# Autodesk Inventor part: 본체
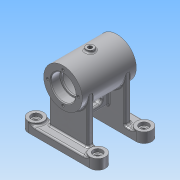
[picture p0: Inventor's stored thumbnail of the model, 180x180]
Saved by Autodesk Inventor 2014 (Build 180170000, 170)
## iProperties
Created: 2015-11
Part Number: 본체
Material: 알루미늄 6061
Document SubType Name: Modeling
Designer: 103-07
Density: 2.71 g/cm^3
Appearance: 알루미늄 - 평지
Mass: 359.155 g
Surface Area: 459.458 cm^2
Volume: 132.529 cm^3
Author: 103-07
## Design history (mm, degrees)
sketch "스케치1"
  geometry: L1 (-40, 40)-(40, 40); L2 (-40, 20)-(40, 20); L3 (-40, -20)-(40, -20); L4 (-40, -40)-(40, -40); A1 r 10 centre (-40, 30) between (-40, 40) and (-40, 20); A2 r 10 centre (40, 30) between (40, 40) and (40, 20); A3 r 10 centre (-40, -30) between (-40, -20) and (-40, -40); A4 r 10 centre (40, -30) between (40, -20) and (40, -40); 3 further points
  constraints: 8 end point, 8 point on circle, 7 tangent, 4 centre point, 3 equal radius, 2 horizontal, 2 midpoint, 2 vertical alignment, 1 horizontal alignment, 1 parallel
  dimensions: "d0" = 20 diameter of A1; "d1" = 80 distance of A2.centre A1.centre; "d2" = 80 distance between parallel lines of L4 L1; "d3" = 40 distance from line of L4 point (0, 0)
extrude "돌출1" new body sketch "스케치1" distance "d4" = 10; taper "d5" = 0 deg
extrude "돌출2" join sketch "스케치1" distance "d6" = 13; taper "d7" = 0 deg
node "작업 평면1"
sketch "스케치2"
  geometry: L1 (-35, 68)-(35, 68); L2 (-20, 0)-(-40, 0) reference; L3 (-35, 68)-(-35, 93); L4 (-35, 93)-(35, 93); L5 (35, 93)-(35, 68); 2 further points
  constraints: 8 end point, 2 perpendicular, 1 horizontal, 1 midpoint, 1 parallel, 1 vertical alignment
  dimensions: "d9" = 70 distance of L1.start L1.end; "d10" = 68 distance between parallel lines of L2 L1; "d11" = 50 diameter of L4 L1
revolve "회전1" sketch "스케치2" stored, may be unused: angle "d12" = 90 deg
sketch "스케치5"
  geometry: L1 (0, 10)-(80, 10) reference; L2 (15, 68)-(15, 10); L3 (65, 68)-(65, 10); L4 (15, 68)-(65, 68); A1 r 25 centre (40, 68) between (15, 68) and (65, 68) reference; 1 further point
  constraints: 6 end point, 3 perpendicular, 2 point on circle, 2 point on line, 2 tangent
extrude "돌출3" join sketch "스케치5" distance "d15" = 8; taper "d16" = 0 deg
node "작업 평면5"
sketch "스케치7"
  geometry: L1 (-25, 20)-(25, 20) reference; L2 (25, -20)-(-25, -20) reference; L3 (-25, -28)-(25, -28) reference; L4 (25, 28)-(-25, 28) reference; L5 (-4, 28)-(4, 28); L6 (4, 28)-(4, -28); L7 (4, -28)-(-4, -28); L8 (-4, -28)-(-4, 28); L9 (-4, 28)-(4, -28); L10 (4, 28)-(-4, -28); 1 further point
  constraints: 12 end point, 2 midpoint, 2 parallel, 1 horizontal, 1 perpendicular, 1 point on line
  dimensions: "d23" = 8 distance of L5.start L5.end
extrude "돌출4" join sketch "스케치7" stored distance "d24" = 8; taper "d25" = 0 deg
sketch "스케치8"
  geometry: L1 (0, 40)-(0, 0) reference; L2 (13.5, 28)-(13.5, 12); L3 (6.5, 12)-(6.5, 28); L4 (-23, -20)-(-23, 0) reference; A1 r 3.5 centre (10, 12) between (6.5, 12) and (13.5, 12); A2 r 3.5 centre (10, 28) between (13.5, 28) and (6.5, 28); 3 further points
  constraints: 4 end point, 4 point on circle, 4 tangent, 2 centre point, 2 midpoint, 2 parallel, 1 horizontal alignment
  dimensions: "d26" = 23 dimension on A1 A2; "d27" = 33 distance from line of L4 A1.centre; "d28" = 3.5 radius of A1
extrude "돌출5" cut sketch "스케치8" stored distance "d29" = 0; taper "d30" = 0 deg
node "작업 평면6"
sketch "스케치9"
  geometry: C1 r 5 at (0, 0); 1 further point
  constraints: 1 centre point, 1 coincident
  dimensions: "d32" = 10 diameter of C1
extrude "돌출6" join sketch "스케치9" stored distance "d33" = 8; taper "d34" = 0 deg
node "작업 평면7"
sketch "스케치10"
  geometry: L1 (-35, 43)-(-35, 93) reference; L2 (35, 43)-(35, 93) reference; L3 (-35, 68)-(35, 68); L4 (-35, 68)-(-35, 84); L5 (-35, 84)-(-23, 84); L6 (-23, 84)-(-23, 82); L7 (-23, 82)-(-21, 82); L8 (-21, 82)-(-21, 89); L9 (-21, 89)-(21, 89); L10 (21, 89)-(21, 82); L11 (21, 82)-(23, 82); L12 (23, 82)-(23, 84); L13 (23, 84)-(35, 84); L14 (35, 84)-(35, 68); 1 further point
  constraints: 24 end point, 6 parallel, 3 perpendicular, 2 midpoint, 2 point on line, 1 collinear
  dimensions: "d36" = 32 diameter of L5 L3; "d37" = 28 diameter of L7 L3; "d38" = 42 diameter of L9 L3; "d39" = 28 diameter of L11 L3; "d40" = 32 diameter of L13 L3; "d41" = 12 distance of L4.end L5.end; "d42" = 12 distance of L12.end L13.end; "d43" = 42 distance of L8.end L9.end; "d44" = 2 distance of L6.end L7.end
revolve "회전2" sketch "스케치10" stored, may be unused: angle "d45" = 90 deg
hole "구멍1" diameter "d48" = 6; stored, may be unused: countersink angle "d52" = 90 deg, drill point angle "d54" = 118 deg; dims "d46" = 10, "d47" = 10, "d49" = 6, "d50" = 12, "d51" = 4, "d53" = 8
hole "구멍2" diameter "d57" = 6; stored, may be unused: countersink angle "d61" = 90 deg, drill point angle "d63" = 118 deg; dims "d55" = 10, "d56" = 10, "d58" = 6, "d59" = 12, "d60" = 4, "d62" = 8
hole "구멍3" diameter "d66" = 6; stored, may be unused: countersink angle "d70" = 90 deg, drill point angle "d72" = 118 deg; dims "d64" = 10, "d65" = 10, "d67" = 6, "d68" = 12, "d69" = 4, "d71" = 8
hole "구멍4" diameter "d75" = 6; stored, may be unused: countersink angle "d79" = 90 deg, drill point angle "d81" = 118 deg; dims "d73" = 10, "d74" = 10, "d76" = 6, "d77" = 12, "d78" = 4, "d80" = 8
sketch "스케치12"
  geometry: C1 r 16 at (0, 0) reference; C2 r 25 at (0, 0) reference; A1 r 20 centre (0, 0) between (0, 20) and (0, -20); 3 further points
  constraints: 4 point on circle, 2 horizontal alignment, 2 vertical alignment, 1 centre point, 1 coincident
  dimensions: "d83" = 40 diameter of A1
hole "구멍5" sketch "스케치12" at (0, 20), (0, -20), (20, 0), (-20, 0) diameter "d84" = 3.242; stored, may be unused: countersink angle "d88" = 90 deg, drill point angle "d90" = 118 deg; dims "d85" = 8, "d86" = 12, "d87" = 4, "d89" = 10
node "작업 평면8"
sketch "스케치13"
  geometry: L1 (-35, 25)-(-35, -25) reference; L2 (35, 25)-(-35, 25) reference; 2 further points
  constraints: 1 other
  dimensions: "d91" = 35 distance from line of point (0, 0) L1; "d92" = 25 distance from line of L2 point (0, 0)
feature "엠보싱1" sketch "스케치13" dims "d93" = 0.5, "d94" = 0
node "작업 평면9"
sketch "스케치14"
  geometry: L1 (0, 68)-(14, 43.751); C1 r 14 at (0, 68) reference; 1 further point
  constraints: 2 end point
  dimensions: "d96" = 30 deg dimension on L1.start point (0, 0) L1.end; "d97" = 28 distance of L1.start L1.end
node "작업 평면10"
sketch "스케치15"
  geometry: C1 r 6 at (0, 0); 2 further points
  constraints: 1 centre point, 1 coincident
  dimensions: "d98" = 12 diameter of C1
extrude "돌출7" join sketch "스케치15" stored distance "d99" = 0; taper "d100" = 0 deg
hole "구멍6" diameter "d103" = 5.188; stored, may be unused: countersink angle "d107" = 90 deg, drill point angle "d109" = 0 deg; dims "d101" = 10, "d102" = 10, "d104" = 8, "d105" = 12, "d106" = 4, "d108" = 10
hole "구멍7" diameter "d112" = 5.188; stored, may be unused: countersink angle "d116" = 90 deg, drill point angle "d118" = 0 deg; dims "d110" = 10, "d111" = 10, "d113" = 8, "d114" = 12, "d115" = 4, "d117" = 10
chamfer "모따기1" distance "d119" = 1; stored, may be unused: second distance "d120" = 2, angle "d121" = 45 deg
fillet "모깎기1" dims "d122" = 0.3, "d123" = 3, "d124" = 2
fillet "모깎기3" dims "d126" = 2
node "솔리드1"
mirror "대칭1"
mirror "대칭2"
node "투영된 루프2"
other parameters: "d8" = 0, "d22" = -23, "d31" = 96, "d35" = 0, "d95" = 0
